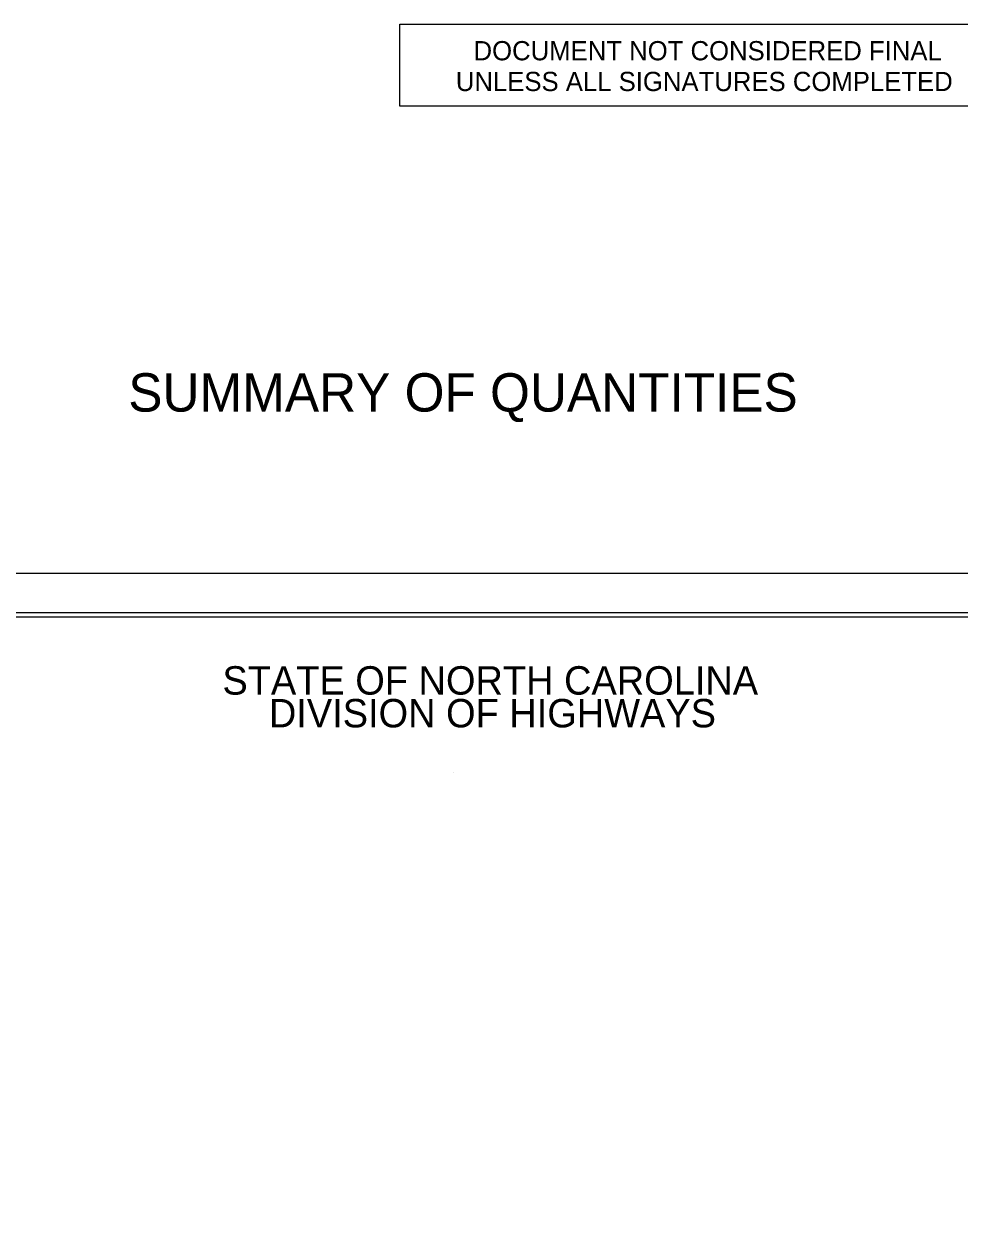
# Model space of a CAD drawing. Extents: x 1729625 to 1732014, y 538843 to 541329.
# Drawn here: x 1730486 to 1731022, y 540638 to 541329 of the extents above; entities that cross this region are included whole.
import ezdxf

# ---------------------------------------------------------------- set-up
doc = ezdxf.new("R2010")
doc.units = 0
for name, color, linetype in [('Sheet Cutting Line CELL', 7, 'Continuous'), ('Sheet Plot Border Inside CELL', 7, 'Continuous'), ('Sheet Plot Border Outside CELL', 7, 'Continuous'), ('Sheet Sticker Exception Certification CELL', 7, 'Continuous'), ('Sheet Summary CELL', 7, 'Continuous')]:
    doc.layers.add(name, color=color, linetype=linetype)

msp = doc.modelspace()

# ---------------------------------------------------------------- linework, layer by layer
at = {"layer": 'Sheet Cutting Line CELL'}
msp.add_line((1731499.47, 541014.91), (1729815.47, 541014.91), dxfattribs=at)
at = {"layer": 'Sheet Plot Border Inside CELL'}
msp.add_lwpolyline([(1731494.97, 540992.46), (1729828.47, 540992.46), (1729828.47, 539937.36), (1731494.97, 539937.36)], close=True, dxfattribs=at)
at = {"layer": 'Sheet Plot Border Outside CELL'}
msp.add_lwpolyline([(1731499.47, 541014.91), (1729815.47, 541014.91), (1729815.47, 539914.91), (1731499.47, 539914.91)], close=True, dxfattribs=at)
at = {"layer": 'Sheet Sticker Exception Certification CELL'}
for p, q in [((1730701.49, 541282.27), (1730701.49, 541329.27)), ((1730701.49, 541329.27), (1731101.56, 541329.27)), ((1731101.56, 541282.27), (1730701.49, 541282.27))]:
    msp.add_line(p, q, dxfattribs=at)
at = {"layer": 'Sheet Summary CELL'}
msp.add_line((1730732.07, 540901.11), (1730732.07, 540901.11), dxfattribs=at)
msp.add_lwpolyline([(1731482.47, 540989.91), (1729982.47, 540989.91), (1729982.47, 539939.91), (1731482.47, 539939.91)], close=True, dxfattribs=at)

# ---------------------------------------------------------------- texts
at = {"layer": 'Sheet Sticker Exception Certification CELL'}
for s, p in [('DOCUMENT NOT CONSIDERED FINAL', (1730743.63, 541308.58)), ('UNLESS ALL SIGNATURES COMPLETED', (1730733.49, 541290.98))]:
    msp.add_text(s, height=11, dxfattribs=at).set_placement(p)
at = {"layer": 'Sheet Summary CELL'}
for s, height, p in [('SUMMARY OF QUANTITIES', 21.9501, (1730545.97, 541107.58)), ('STATE OF NORTH CAROLINA', 16.2501, (1730599.87, 540945.66)), ('DIVISION OF HIGHWAYS', 16.2501, (1730626.47, 540926.91))]:
    msp.add_text(s, height=height, dxfattribs=at).set_placement(p)

doc.saveas('drawing.dxf')
